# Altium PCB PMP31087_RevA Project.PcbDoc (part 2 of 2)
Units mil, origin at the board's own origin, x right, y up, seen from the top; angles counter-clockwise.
Board outline 6012.5 x 1662.5 mil, 2 copper layers (Top Layer, Bottom Layer), stack 62 mil thick; 71 components, 40 nets, 159 pads, 54 vias.
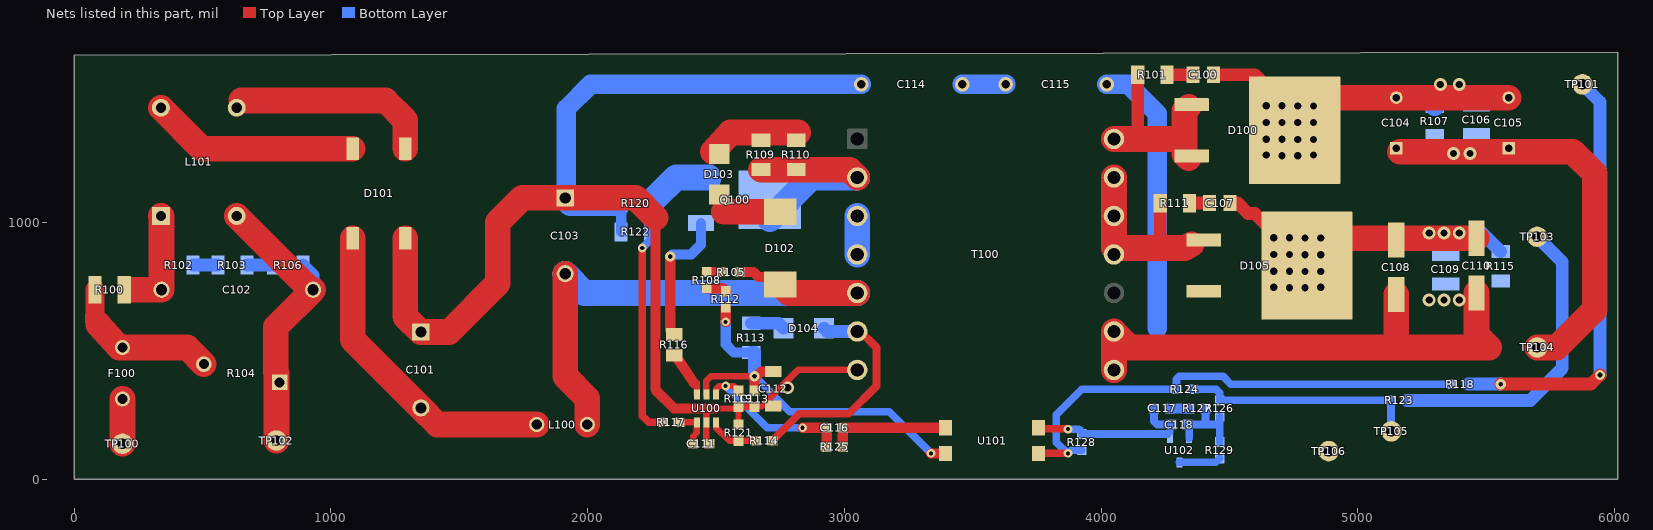
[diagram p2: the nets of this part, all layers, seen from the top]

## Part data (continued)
U100: library part CMP-0078369-1, "High-Efficiency Low-Cost Flyback Controller with Secondary-Side Regulation, DBV0006A (SOT-23-6)", Alternate Manufacturer="Texas Instruments"
U101: library part CMP-0006181-3, "Optocoupler, 5 kV, 80-160% CTR, SMT", Manufacturer="Fairchild Semiconductor", Supplier Part Number 1=FOD817ASDCT-ND, Voltage_Isolation_Vrms=5kV
U102: library part CMP-0084731-1, "High Bandwidth Low-Iq Programmable Shunt Regulator, DBZ0003A (SOT-23-3)", Alternate Manufacturer="Texas Instruments"

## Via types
v1: diameter 50, hole 28, Top Layer to Bottom Layer, 43 vias
v2: diameter 34, hole 16, Top Layer to Bottom Layer, 7 vias
v3: diameter 40, hole 18, Top Layer to Bottom Layer, 4 vias

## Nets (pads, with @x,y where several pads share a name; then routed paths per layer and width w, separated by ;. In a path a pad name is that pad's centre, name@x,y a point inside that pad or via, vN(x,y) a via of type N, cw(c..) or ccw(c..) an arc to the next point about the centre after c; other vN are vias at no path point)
GND: C104.1 C105.1 C106.2 C108.1 C109.2 C110.1 C115.1 R107.1 R115.1 R129.1 T100.8 T100.9 TP104.1 TP106.1 U102.3 | length 4936.1
  Top Layer w100: T100.8@4050,425 T100.9@4050,575 4112.5,512.5 5137.5,512.5 ; C108.1@5150,718.7 5150,525 5137.5,512.5 ; C104.1@5164.07,1275 5372.25,1275 5437.5,1275 5587.5,1275 5837.5,1275 5922.5,1190 5922.5,660 5893.75,631.25 5775,512.5 TP104.1@5698.5,512.5 ; C110.1@5462.5,725 5462.5,562.5 5512.5,512.5 5462.5,512.5 5137.5,512.5
  Bottom Layer w30: U102.3@4305.41,65.26 4446.75,65.26 R129.1@4462.5,81
  Bottom Layer w75: C115.1@4021.85,1537.5 4105.51,1537.5 4218.5,1424.51 4218.5,587.17
  other v1: 5278,697.44 5336,697.44 5394.96,697.44 5372.25,1268.75 5437.5,1268.75
NetC100_1: C100.1 R101.1 | length 100.4
  Top Layer w50: R101.1@4257.09,1575 C100.1@4357.5,1575
NetC100_2: C100.2 C104.2 C105.2 C106.1 D100.2 R107.2 R118.1 TP101.1 | length 3295.7
  Top Layer w50: C100.2@4437.5,1575 4598.62,1575 4743.01,1430.61 D100.2@4743.01,1400.24 ; v3(5557.04,369.75) 5908,369.75 v3(5943.66,405.41)
  Top Layer w100: D100.2@4745.63,1403.5 D100.2@4780.87,1438.74 ; D100.2@4763.25,1400.24 4825.55,1400.24 4911.24,1485.93 C104.2@5150,1485.93 C105.2@5587.5,1485.93
  Bottom Layer w50: R118.1@5430.17,369.75 v3(5557.04,369.75) ; TP101.1@5875,1537.5 5943.66,1468.84 v3(5943.66,405.41)
  Bottom Layer w75: R107.2@5300,1451.67 5334.25,1485.93 C105.2@5587.5,1485.93
  other v1: 4704.42,1259.75 4765.86,1259.75 4643.26,1261.87 4827.02,1261.87 4765.86,1323.24 4827.02,1323.24 4643.26,1323.91 4704.42,1323.91 4765.86,1388.49 4827.02,1388.49 4643.26,1389.16 4704.42,1389.16 4643.26,1454.41 4704.42,1454.41 4765.86,1453.74 4827.02,1453.74 5321.5,1537.5 5394.96,1537.5
NetC101_2: C101.2 D101.1 L100.1 | length 1248.8
  Top Layer w100: D101.1@1085.14,938 1085.14,542.22 C101.2@1350,277.36 1414.86,212.5 L100.1@1801.57,212.5
NetC102_1: C102.1 L101.1 R100.2 R102.2 | length 503.3
  Top Layer w100: 225,737.5 C102.1@339.86,737.5 339.86,1022.64 L101.1@337.5,1025
  Bottom Layer w50: C102.1@339.86,737.5 339.86,824.7 R102.2@348.91,833.75
NetC102_2: C102.2 L101.2 R104.1 R106.1 TP102.1 | length 1178.4
  Top Layer w100: L101.2@632.78,1025 920.28,737.5 C102.2@930.41,737.5 785.14,592.22 785.14,414.57 cw(c785.14,412.2) 787.5,412.2 TP102.1@787.5,150
  Bottom Layer w50: R106.1@890.84,833.75 930.41,794.17 C102.2@930.41,737.5
NetC103_2: C103.2 D102.2 L100.2 R105.2 T100.5 | length 2285
  Top Layer w40: R105.2@2590.39,806.5 2646.13,806.5 2665.13,787.5 2720.77,787.5 D102.2@2750,758.27
  Top Layer w100: C103.2@1912.5,800 1912.5,400 1998.43,314.07 L100.2@1998.43,212.5 ; D102.2@2750,758.27 2783.27,725 T100.5@3050,725
  Bottom Layer w100: C103.2@1912.5,800 1987.5,725 T100.5@3050,725
NetC107_1: C107.1 R111.1 | length 77.9
  Top Layer w50: R111.1@4344.59,1075 C107.1@4422.5,1075
NetC107_2: C107.2 C108.2 C109.1 C110.2 D105.2 R115.2 R123.2 TP103.1 | length 2562.9
  Top Layer w50: C107.2@4502.5,1075 4532.03,1075 4572.78,1034.25 4598.62,1034.25 4779.72,853.15 D105.2@4801.57,831.3
  Top Layer w100: D105.2@4774.63,888.75 D105.2@4809.87,923.99 ; D105.2@4776.57,850 4779.72,853.15 4864.17,937.6 C110.2@5462.5,937.6
  Bottom Layer w50: R123.2@5192.16,306.5 5671.5,306.5 5796.59,431.59 5796.59,845.66 TP103.1@5698.5,943.75 ; v1@5406.1,960.4 5482.46,960.4 R115.2@5557.04,885.81
  other v1: 4733.42,745 4794.86,745 4672.26,747.12 4856.02,747.12 4794.86,808.49 4856.02,808.49 4672.26,809.16 4733.42,809.16 4672.26,874.41 4733.42,874.41 4794.86,873.74 4856.02,873.74 4794.86,938.99 4856.02,938.99 4672.26,939.66 4733.42,939.66 5278,958.86 5336,958.86 5394.96,958.86
NetC111_1: C111.1 R117.1 U100.4 | length 158
  Top Layer w25: R117.1@2356.5,220.87 U100.4@2425.1,220.87 2425.1,180.51 2410.63,166.04 C111.1@2410.63,137.5
NetC114_1: C114.1 C115.2 | length 168.8
  Bottom Layer w75: C114.1@3459.35,1537.5 C115.2@3628.15,1537.5
NetC116_1: C116.1 R125.2 U101.3 | length 475.4
  Top Layer w40: R125.2@2994,125 C116.1@2994,200 U101.3@3394.39,200
NetC116_2: C116.2 R119.2 R125.1 U100.1 | length 659.2
  Top Layer w25: U100.1@2499.9,329.13 2499.9,349.9 2512.5,362.5 v2(2537.5,362.5) 2569,362.5 R119.2@2587.5,344
  Top Layer w40: v2(2837.5,200) C116.2@2931,200 R125.1@2931,125
  Bottom Layer w25: v2@2835.62,196.62 v2@2837.5,195.57
  Bottom Layer w30: v2(2537.5,362.5) 2700,200 v2(2837.5,200)
NetC117_1: C117.1 C118.2 R128.1 U101.2 U102.1 | length 683
  Top Layer w30: U101.2@3756.59,200 ccw(c3760.84,200) 3760.84,195.75 3870.22,195.75 cw(c3870.22,194.47) v2(3871.5,194.47)
  Bottom Layer w30: v2(3871.5,194.47) 3906.02,194.47 cw(c3906.02,175.49) R128.1@3925,175.49 4259.55,175.49 4268.01,183.96 4268.01,206.59 C118.2@4273.92,212.5 4218.5,212.5 4206,225 C117.1@4206,275
NetC117_2: C117.2 R127.2 | length 74.5
  Bottom Layer w40: C117.2@4269,275 R127.2@4343.5,275
NetC118_1: C118.1 R126.1 R127.1 R129.2 U102.2 | length 343.4
  Bottom Layer w30: U102.2@4342.81,159.74 4342.81,206.59 C118.1@4336.91,212.5 4406.5,212.5 ; R127.1@4406.5,275 4406.5,212.5 ; R129.2@4462.5,144 4462.5,213.98 ; R126.1@4462.5,243.5 4462.5,213.98 ; 4406.5,212.5 4461.02,212.5 4462.5,213.98
NetD100_1: D100.1 D100.3 R101.2 T100.14 | length 738.6
  Top Layer w50: 4142.91,1325 R101.2@4142.91,1575
  Top Layer w100: T100.14@4050,1325 4142.91,1325 4325,1325 ; D100.3@4341.44,1250 4325,1266.44 4325,1325 ; D100.1@4341.44,1450 4325,1433.56 4325,1325
NetD101_3: D101.3 L101.3 | length 782.5
  Top Layer w100: L101.3@650,1475 1212.5,1475 1289.86,1397.64 D101.3@1289.86,1287
NetD101_4: D101.4 L101.4 | length 813.6
  Top Layer w100: L101.4@337.5,1446.26 496.76,1287 D101.4@1085.14,1287
NetD102_1: D102.1 D103.1 | length 294.5
  Top Layer w40: D103.1@2512.5,1108.76 2512.5,1058.9 2529.67,1041.73
  Top Layer w100: 2529.67,1041.73 D102.1@2750,1041.73
NetD103_2: D103.2 R109.2 R110.2 | length 364.8
  Top Layer w100: D103.2@2487.6,1275.1 2556.54,1350 2819.52,1350
NetD104_1: D104.1 R113.1 | length 133.8
  Bottom Layer w50: R113.1@2637.5,607.09 2743.6,607.09 D104.1@2763.19,587.5
NetD105_1: D105.1 D105.3 R111.2 T100.11 T100.12 T100.13 | length 752.9
  Top Layer w50: R111.2@4230.41,1075 4230.41,907.09 4237.5,900
  Top Layer w100: T100.11@4050,900 T100.12@4050,1025 T100.13@4050,1175 ; T100.11@4056.38,900 4237.5,900 4325,900 D105.1@4352.56,914.96
NetF100_1: F100.1 R100.1 R104.2 | length 600.5
  Top Layer w75: 80.1,614.22 80.41,674.51 R100.1@80.41,737.5
  Top Layer w100: 94.25,601.75 175,512.2 F100.1@187.5,512.2 440.3,512.2 R104.2@504.86,447.64
NetF100_2: F100.2 TP100.1 | length 174.7
  Top Layer w100: TP100.1@187.5,137.5 F100.2@187.5,312.2
NetQ100_1: Q100.1 R116.2 | length 531.2
  Top Layer w40: v3(2322.03,867.17) 2322.03,580.46 R116.2@2344.99,557.5
  Bottom Layer w40: v3@2329.86,875 2403.64,875 2441.14,912.5 Q100.1@2441.14,997.74
NetQ100_2: Q100.2 R109.1 R110.1 T100.2 | length 796
  Top Layer w100: R109.1@2675,1205.41 R110.1@2812.5,1205.41 3019.59,1205.41 T100.2@3050,1175
  Bottom Layer w100: Q100.2@2708.86,1012.5 2871.36,1175 T100.2@3050,1175
NetQ100_3: Q100.3 R117.2 R120.2 R122.2 | length 1176.9
  Top Layer w30: v2(2212.5,900) 2212.5,245.87 2237.5,220.87 R117.2@2293.5,220.87
  Bottom Layer w30: v2(2212.5,900) 2244.59,932.09 R122.2@2244.59,962.5
  Bottom Layer w50: R122.2@2244.59,962.5 R120.2@2244.59,1075
  Bottom Layer w100: R120.2@2262.5,1093.75 2344.59,1175 Q100.3@2472.21,1175
NetR102_1: R102.1 R103.2 | length 96.1
  Bottom Layer w50: R102.1@463.09,833.75 R103.2@559.16,833.75
NetR103_1: R103.1 R106.2 | length 103.3
  Bottom Layer w50: R103.1@673.34,833.75 R106.2@776.66,833.75
NetR105_1: R105.1 R108.2 | length 63.5
  Top Layer w40: R108.2@2463.9,806.5 R105.1@2527.4,806.5
NetR108_1: R108.1 R112.2 | length 78.6
  Top Layer w40: R108.1@2463.9,743.5 2525.49,743.5 R112.2@2537.5,731.5
NetR114_1: R114.1 R121.2 U100.6 | length 198.2
  Top Layer w25: U100.6@2499.9,220.87 2499.9,200.1 2550.98,149.02 R121.2@2587.5,149.02 2655.61,149.02 R114.1@2656,148.62
NetR116_1: R116.1 U100.3 | length 185.6
  Top Layer w25: R116.1@2337.5,482.5 R116.1@2347.5,472.5 ; 2412.5,375 2425.1,375 U100.3@2425.1,329.13
  Top Layer w40: R116.1@2350,469.19 2412.5,375
NetR118_2: R118.2 R124.1 R128.2 U101.1 | length 1966
  Top Layer w30: U101.1@3755.61,100 v2(3871.5,100)
  Bottom Layer w30: R128.2@3925,112.5 3884,112.5 v2(3871.5,100) 3869,100 3825,144 3825,250 3925,350 R124.1@4293.5,350 4293.5,388.09 4305.41,400 4475,400 4505.25,369.75 R118.2@5348.75,369.75
NetR123_1: R123.1 R124.2 R126.2 TP105.1 | length 926.8
  Bottom Layer w30: R124.2@4356.5,350 4447.52,350 4462.53,334.98 ; 4462.5,334.95 R126.2@4462.5,306.5 R123.1@5120.32,306.5 ; R123.1@5124.49,310.89 ccw(c5126.17,310.89) 5124.98,309.7 5128.19,306.5 R123.1@5129.17,306.5 5129.17,187.04 TP105.1@5130.5,185.71
NetT100_3: T100.3 T100.4 | length 150
  Bottom Layer w100: T100.4@3050,875 T100.3@3050,1025
PGND: C101.1 C103.1 C111.2 C112.2 C113.2 C114.2 D101.2 R119.1 R120.1 R121.1 R122.1 T100.7 U100.5 | length 5287.7
  Top Layer w25: C111.2@2473.62,137.5 2462.5,148.62 U100.5@2462.5,220.87 2462.5,257.38 2480.12,275 ; 2499.9,275 2568.5,275 ; R121.1@2587.5,212.01 R119.1@2587.5,281 C113.2@2650,281 2653.02,284.02 2678.54,284.02 2819.52,425 T100.7@3050,425
  Top Layer w40: 2263.82,1018.17 2263.82,348.68 2337.5,275 2480.12,275 2499.9,275
  Top Layer w100: D101.2@1289.86,938 1289.86,632.78 C101.1@1350,572.64 1460.14,572.64 1650,762.5 1650,1000 1745.28,1095.28 C103.1@1912.5,1095.28 2186.71,1095.28 2263.82,1018.17
  Bottom Layer w40: R122.1@2130.41,962.5 R120.1@2130.41,1075
  Bottom Layer w75: C103.1@1912.5,1095.28 1916.18,1098.96 1916.18,1442.75 2010.93,1537.5 C114.2@3065.65,1537.5
  Bottom Layer w100: C103.1@1912.5,1095.28 1932.78,1075 2104.67,1075
  other v1: 2779.65,355.94
VAUX: D104.2 R114.2 T100.6 | length 880
  Top Layer w30: R114.2@2719,148.62 2824.74,254.37 3016.87,254.37 3125,362.5 3125,512.5 3062.5,575 T100.6@3050,575
  Bottom Layer w50: D104.2@2920.67,587.5 2933.17,575 T100.6@3050,575
VDD: C112.1 C113.1 R112.1 R113.2 U100.2 U101.4 | length 1594.1
  Top Layer w25: U100.2@2462.5,329.13 2462.5,382.38 2480.12,400 v3@2632.38,400
  Top Layer w40: v2(2537.5,612.5) R112.1@2537.5,665.55 ; C113.1@2650,344 v3(2650,400) 2657.43,400 2676.56,419.13 C112.1@2722.8,419.13 ; v2(3337.5,100) U101.4@3393.41,100
  Bottom Layer w30: v3(2650,400) 2787.5,262.5 3175,262.5 v2(3337.5,100)
  Bottom Layer w40: v2(2537.5,612.5) 2537.5,525 2569.59,492.91 R113.2@2637.5,492.91
  Bottom Layer w50: R113.2@2637.5,492.91 2650,492.91 v3(2650,400)
pads on no net: T100.1 T100.10

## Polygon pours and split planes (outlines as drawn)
NetD105_1 on Top Layer "TOP_LAYER_NETD105_1_P016" (solid, remove dead copper, pour order 16): 4464.39,888.75 ccw(c4405.69,905.55) 4422.5,964.25 4031.11,964.25 ccw(c4047.68,916.57) 4000,900 4000,727.11 ccw(c4031.11,727.11) 4031.11,696 4445.43,696 ccw(c4445.43,714.96) 4464.39,714.96
GND on Top Layer "TOP_LAYER_GND_P011" (solid, remove dead copper, pour order 11): 4036.42,65.25 cw(c4036.42,102.31) 3999.36,102.31 3999.36,634.14 cw(c4038.25,634.14) 4038.25,673.03 4460.22,673.03 cw(c4460.22,630.75) 4502.5,630.75 ccw(c4527.25,630.75) 4527.25,606 5056.93,606 ccw(c5056.93,653.07) 5104,653.07 5104,1316.8 cw(c5158.22,1316.8) 5158.22,1371.02 5937.75,1371.02 cw(c5936.28,1318.28) 5989.02,1316.8 5989.02,116.52 cw(c5937.75,116.52) 5937.75,65.25
NetC103_2 on Top Layer "TOP_LAYER_NETC103_2_P013" (solid, remove dead copper, pour order 13): 2585.82,835.04 2933.96,835.04 cw(c2933.96,806.5) 2962.5,806.5 2962.5,663.08 cw(c2945.42,663.08) 2945.42,646 2613.88,646 cw(c2613.88,674.06) 2585.82,674.06 2585.82,813.69 cw(c2605.89,813.69) 2605.89,833.76
NetD102_1 on Top Layer "TOP_LAYER_NETD102_1_P012" (solid, remove dead copper, pour order 12): 2473.16,1095.28 2863.22,1095.28 cw(c2863.22,1073) 2885.5,1073 2885.5,947.54 cw(c2863.75,947.54) 2863.75,925.79 2501.59,925.79 cw(c2501.59,953.75) 2473.62,953.75
NetD100_1 on Top Layer "TOP_LAYER_NETD100_1_P007" (solid, remove dead copper, pour order 7): 4237.5,1275 cw(c4237.5,1255.41) 4257.09,1255.41 4257.09,1206.25 ccw(c4263.34,1206.25) 4263.34,1200 4385,1200 ccw(c4385,1237.5) 4422.5,1237.5 4422.5,1477.5 ccw(c4400,1477.5) 4400,1500 4114.07,1500 ccw(c4114.07,1485.93) 4100,1485.93 4100,1412.5 cw(c4087.5,1412.5) 4087.5,1400 4025,1400 ccw(c4025,1375) 4000,1375 4000,1296.85 ccw(c4021.85,1296.85) 4021.85,1275
NetC107_2 on Top Layer "TOP_LAYER_NETC107_2_P006" (solid, remove dead copper, pour order 6): 4582.53,600 cw(c4582.53,645.03) 4537.5,645.03 4537.5,1037.5 cw(c4562.5,1037.5) 4562.5,1062.5 5698.5,1062.5 cw(c5708.51,1012.24) 5758.76,1022.25 5758.76,873.74 cw(c5710.56,885.67) 5698.5,837.5 5091.42,837.5 ccw(c5091.42,812.5) 5066.42,812.5 5066.42,632.67 cw(c5033.76,632.67) 5033.75,600
NetC100_2 on Top Layer "TOP_LAYER_NETC100_2_P005" (solid, remove dead copper, pour order 5): 4950,1100 ccw(c4950,1137.5) 4987.5,1137.5 4987.5,1275 cw(c5075,1275) 5075,1362.5 5937.5,1362.5 ccw(c5937.5,1425) 6000,1425 6000,1612.5 ccw(c5962.5,1612.5) 5962.5,1650 4612.5,1650 ccw(c4612.5,1600) 4562.5,1600 4562.5,1125 ccw(c4587.5,1125) 4587.5,1100
PGND on Top Layer "TOP_LAYER_PGND_P001" (solid, pour order 1): 1675,725 1870.63,875 1870.63,1054.37 1812.5,1112.5 1733.28,1033.28 1662.5,1033.28
PGND on Top Layer "TOP_LAYER_PGND_P000" (solid, remove dead copper, pour order 0): 1850,1100 2319.43,1100 cw(c2328.47,1015.97) 2412.5,1025 2412.5,700 ccw(c2500,687.5) 2487.5,600 3037.5,600 cw(c3037.5,500) 3137.5,500 3137.5,62.5 cw(c3100,62.5) 3100,25 1950,25 cw(c1950,125) 1850,125 1850,180.51
NetC100_2 on Bottom Layer "BOTTOM_LAYER_NETC100_2_P003" (solid, remove dead copper, pour order 3): 5075.22,1609.68 5076.72,1434.2 ccw(c5094.58,1438.87) 5099.24,1421.01 5914.37,1421.01 ccw(c5908.72,1451.44) 5939.15,1457.09 5939.15,1609.68 ccw(c5902.84,1593.75) 5886.89,1630.06 5099.24,1630.06 ccw(c5097.41,1607.86)
NetC107_2 on Bottom Layer "BOTTOM_LAYER_NETC107_2_P004" (solid, remove dead copper, pour order 4): 5241.44,879.22 ccw(c5272.41,879.22) 5272.41,848.25 5747.72,848.25 ccw(c5750.99,882.5) 5785.24,879.22 5785.24,978.75 ccw(c5752.64,973.83) 5747.72,1006.44 5277.69,1015 ccw(c5277.69,978.75) 5241.44,978.75
GND on Bottom Layer "BOTTOM_LAYER_GND_P015" (solid, remove dead copper, pour order 15): 4006.84,21.75 cw(c4006.84,48.34) 3980.25,48.34 3980.25,572.75 cw(c4045.5,572.75) 4045.5,638 5176.5,638 ccw(c5176.5,703.25) 5241.75,703.25 5241.75,1567.03 cw(c5300,1567.03) 5300,1625.28 5929.74,1625.28 cw(c5929.74,1566) 5989.02,1566 5989.02,58.52 cw(c5952.25,58.52) 5952.25,21.75
NetC107_2 on Bottom Layer "BOTTOM_LAYER_NETC107_2_P014" (solid, remove dead copper, pour order 14): 4560.25,1027.93 cw(c4587.5,1027.93) 4587.5,1055.18 5165.32,1055.18 cw(c5165.32,1029.5) 5191,1029.5 5191,641 cw(c5150,641) 5150,600 4589.78,600 cw(c4589.78,629.53) 4560.25,629.53
NetC100_2 on Bottom Layer "BOTTOM_LAYER_NETC100_2_P010" (solid, remove dead copper, pour order 10): 4562.5,1587.75 4562.5,1604.5 cw(c4589.25,1604.5) 4589.25,1631.25 5154.75,1631.25 cw(c5154.75,1595) 5191,1595 5191,1128.5 cw(c5162.5,1128.5) 5162.5,1100 4584,1100 cw(c4584,1123.75) 4560.25,1123.75
PGND on Bottom Layer "BOTTOM_LAYER_PGND_P009" (solid, remove dead copper, pour order 9): 1587.5,964.68 1587.5,125 ccw(c1675,125) 1675,37.5 3101.52,37.5 ccw(c3101.52,62.5) 3126.52,62.5 3126.52,423.48 ccw(c3050,423.48) 3050,500 2220.71,500 cw(c2220.71,570.71) 2150,570.71 2150,885.63 ccw(c2062.5,885.63) 2062.5,973.13
PGND on Bottom Layer "BOTTOM_LAYER_PGND_P008" (solid, remove dead copper, pour order 8): 1677.18,875 cw(c1677.18,964.68) 1587.5,964.68 1587.5,1287.5 cw(c1687.5,1287.5) 1687.5,1387.5 2100.13,1387.5 cw(c2100.13,1337.63) 2150,1337.63 2150,925 cw(c2100,925) 2100,875
NetQ100_2 on Bottom Layer "BOTTOM_LAYER_NETQ100_2_P002" (solid, pour order 2): 2601.29,947.51 cw(c2598.25,976.17) 2569.59,973.13 2569.59,1294.59 cw(c2625,1294.59) 2625,1350 2900,1350 cw(c2900,1287.5) 2962.5,1287.5 2962.5,973.13 cw(c2926.77,982.48) 2917.42,946.75

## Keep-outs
Keep-Out Layer:
  text ".Layer_Name" at 577,-858.49 h60

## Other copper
Top Layer:
  text ".Layer_Name" at 577,-858.49 h60
Bottom Layer:
  text ".Layer_Name" at 577,-858.49 h60

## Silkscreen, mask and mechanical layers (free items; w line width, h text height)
Top Overlay:
  text "PMP31087_RevA" at 5215.12,70.75 h60
  text ".Layer_Name" at 577,-858.49 h40
Bottom Overlay:
  text ".Layer_Name" at 577,-858.49 h40
Top Paste:
  text ".Layer_Name" at 577,-858.49 h60
Bottom Paste:
  text ".Layer_Name" at 577,-858.49 h60
Top Solder:
  text ".Layer_Name" at 577,-858.49 h60
  text ".Layer_Name" at 577,-858.49 h60
Bottom Solder:
  text ".Layer_Name" at 577,-858.49 h60
Drill Guide:
  text ".Layer_Name" at 577,-858.49 h60
M1 Board Outline:
  the board outline again, w10
  text ".Layer_Name" at 577,-858.49 h60
M2 Board Dimensions:
  rectangle: 0,-275 125,-150
  rectangle: 125,-400 500,-275
  lines w7: 0,-275 1000,-275 ; 125,-400 125,-150 ; 250,-400 250,-150 ; 500,-400 500,-150 ; 750,-400 750,-150 ; 0,-400 1000,-400 1000,-150 0,-150 0,-400
  text ".Layer_Name" at 577,-858.49 h60
M3 3D STEP Top:
  text ".Layer_Name" at 577,-858.49 h60
M4 3D STEP Bottom:
  text ".Layer_Name" at 577,-858.49 h60
M5 Assembly Top:
  lines w10: -292,-930.17 6308,-930.17 ; -292,-726.83 6310,-726.83 ; -292,-523.5 -292,-1133.5 3713,-1133.5 6310,-1133.5 6310,-523.5 -291.5,-523.5 -291.5,-1133.5 1284,-1133.5 ; 2173,-1133.5 2173,-523.5 ; 3440,-726.83 3440,-523.5 ; 4280,-726.83 4280,-523.5 ; 4902,-1140 4902,-937.17
  text "COMPONENTS MARKED 'DNP' SHOULD NOT BE POPULATED." at 1153.5,-318.5 h60
  text "ASSEMBLY VARIANT:" at 1153,-434 h60
  text ".VariantName" at 2189,-434 h60
  text "PCB VIEWED FROM TOP SIDE" at -228.5,-655.67 h60
  text "BOARD #:" at 2248,-655.67 h60
  text ".PRJ_Number" at 2793.5,-655.67 h60
  text "REV:" at 3638,-655.67 h60
  text ".PCB_Rev" at 3929.5,-655.67 h60
  text "SVN REV:" at 4476,-655.67 h60
  text ".VersionControl_RevNumber" at 4982,-655.67 h60
  text "TID #:" at 2248,-859 h60
  text ".TID" at 2793.5,-859 h60
  text "PLOT NAME =" at -228.5,-1064.34 h60
  text ".plot_File_Name" at 577,-1064.34 h60
  text "GENERATED    :" at 2250,-1064.34 h60
  text ".Print_Date" at 3119.5,-1064.34 h60
  text ".Print_Time" at 3848.5,-1064.34 h60
  text "TEXAS INSTRUMENTS" at 5113,-1064.34 h60
M6 Assembly Bottom:
  lines w10: -292.5,-727.33 6309.5,-727.33 ; -290.5,-930.67 6309.5,-930.67 ; 1115.5,-1140.5 1115.5,-937.67 ; 1737.5,-727.33 1737.5,-524 ; 2577.5,-727.33 2577.5,-524 ; 3844.5,-1134 3844.5,-524 ; 4733.5,-1134 6309,-1134 6309,-524 -292.5,-524 -292.5,-1134 2304.5,-1134 6309.5,-1134 6309.5,-524
  text "COMPONENTS MARKED 'DNP' SHOULD NOT BE POPULATED." at 6102,-318 h60
  text ".VariantName" at 5058,-434 h60
  text "ASSEMBLY VARIANT:" at 6097,-434 h60
  text ".VersionControl_RevNumber" at 1035.5,-656.17 h60
  text "SVN REV:" at 1541.5,-656.17 h60
  text ".PCB_Rev" at 2088,-656.17 h60
  text "REV:" at 2379.5,-656.17 h60
  text ".PRJ_Number" at 3224,-656.17 h60
  text "BOARD #:" at 3769.5,-656.17 h60
  text "PCB VIEWED FROM BOTTOM SIDE" at 6246,-656.17 h60
  text ".TID" at 3224,-859.5 h60
  text "TID #:" at 3769.5,-859.5 h60
  text "TEXAS INSTRUMENTS" at 904.5,-1064.84 h60
  text ".Print_Time" at 2169,-1064.84 h60
  text ".Print_Date" at 2898,-1064.84 h60
  text "GENERATED    :" at 3767.5,-1064.84 h60
  text ".plot_File_Name" at 5440.5,-1064.84 h60
  text "PLOT NAME =" at 6246,-1064.84 h60
M9 Title Sheet:
  drawing of 57 lines, arcs and shapes, not listed
  text "1" at 739.84,8036.5 h70
  text "2" at 3235.5,8036.5 h70
  text "3" at 5724.84,8036.5 h70
  text "4" at 8231.51,8036.5 h70
  text "5" at 10730.5,8036.5 h70
  text "6" at 13235.5,8036.5 h70
  text "A" at -416.5,6893.5 h70
  text "A" at 14383.5,6893.5 h70
  text "B" at -416.5,4513.5 h70
  text "B" at 14383.5,4513.5 h70
  text "C" at -416.5,2138.5 h70
  text "C" at 14383.5,2138.5 h70
  text "PROJECT TITLE:" at 11343.5,277.5 h45
  text ".PRJ_Title" at 11393.5,144.17 h70
  text "DESIGNED FOR:" at 11343.5,-23.5 h45
  text ".PRJ_Customer" at 11393.5,-163.5 h70
  text "D" at -416.5,-231.5 h70
  text "D" at 14383.5,-231.5 h70
  text "FILE NAME:" at 11343.5,-323.5 h45
  text ".PCB_File_Name_No_Path" at 11393.5,-443.5 h70
  text "Texas Instruments (TI) and/or its licensors do not warrant the accuracy or completeness of this specification" at 6374,-605.34 h45
  text "ENGINEER:" at 11343.5,-613.5 h45
  text "LAYOUT BY:" at 12848.5,-613.5 h45
  text "or any information contained therein. TI and/or its licensors do not warrant that this design will meet" at 6329.01,-718 h45
  text ".PRJ_Engineer" at 11393.5,-768.49 h70
  text ".PCB_Layout" at 12899,-768.49 h70
  text "the specifications, will be suitable for your application or fit for any particular purpose, or will operate in" at 6329.01,-830.67 h45
  text ".Layer_Name" at 577,-858.49 h60
  text "ALTIUM DESIGNER VERSION:" at 12848.5,-923.5 h45
  text "an implementation. TI and/or its licensors do not warrant that the design is production worthy. You should" at 6329.01,-943.33 h45
  text "completely validate and test your design implementation to confirm the system functionality for your application." at 6374,-1056 h45
  text ".print_Scale" at 11393.5,-1056.83 h70
  text ".Application_BuildNumber" at 12899,-1056.83 h70
  text "1" at 739.84,-1263.5 h70
  text "2" at 3235.5,-1263.5 h70
  text "3" at 5724.84,-1263.5 h70
  text "4" at 8231.51,-1263.5 h70
  text "5" at 10730.5,-1263.5 h70
  text "6" at 13235.5,-1263.5 h70
M10 Fab Notes:
  lines w20: 14295,871 14295,6451.24
  text ".Layer_Name" at 577,-858.49 h60
M11 Gerber Information:
  lines w10: -292,-930.17 6308,-930.17 ; -292,-726.83 6310,-726.83 ; -292,-523.5 -292,-1133.5 3713,-1133.5 6310,-1133.5 6310,-523.5 -291.5,-523.5 -291.5,-1133.5 1284,-1133.5 ; 2173,-1133.5 2173,-523.5 ; 3440,-726.83 3440,-523.5 ; 4280,-726.83 4280,-523.5 ; 4902,-1140 4902,-937.17
  text "ALL ARTWORK VIEWED FROM TOP SIDE" at -228.5,-655.67 h60
  text "BOARD #:" at 2248,-655.67 h60
  text ".PRJ_Number" at 2793.5,-655.67 h60
  text "REV:" at 3638,-655.67 h60
  text ".PCB_Rev" at 3929.5,-655.67 h60
  text "SVN REV:" at 4476,-655.67 h60
  text ".VersionControl_RevNumber" at 4982,-655.67 h60
  text "LAYER NAME =" at -228.5,-858.49 h60
  text "TID #:" at 2248,-859 h60
  text ".TID" at 2793.5,-859 h60
  text "PLOT NAME =" at -228.5,-1064.34 h60
  text ".plot_File_Name" at 577,-1064.34 h60
  text "GENERATED    :" at 2250,-1064.34 h60
  text ".Print_Date" at 3119.5,-1064.34 h60
  text ".Print_Time" at 3848.5,-1064.34 h60
  text "TEXAS INSTRUMENTS" at 5113,-1064.34 h60
M12 Stackup:
  text ".Layer_Name" at 577,-858.49 h60
M13 Component Bodies Top:
  text ".Layer_Name" at 577,-858.49 h60
M14 Component Bodies Bottom:
  text ".Layer_Name" at 577,-858.49 h60
M15 Courtyards Top:
  text ".Layer_Name" at 577,-858.49 h60
M16 Courtyards Bottom:
  text ".Layer_Name" at 577,-858.49 h60
Drill Drawing:
  text ".Layer_Name" at 577,-858.49 h60
M17 Embedded Cavity:
  text ".Layer_Name" at 577,-858.49 h60
M18 Embedded Assembly:
  text ".Layer_Name" at 577,-858.49 h60
M19 Embedded Keepout:
  text ".Layer_Name" at 577,-858.49 h60

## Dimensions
0,-400 to 1000,-400 on M2 Board Dimensions
0,1650 to 6012.5,0 on M2 Board Dimensions
6012.5,0 to 0,1650 on M2 Board Dimensions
